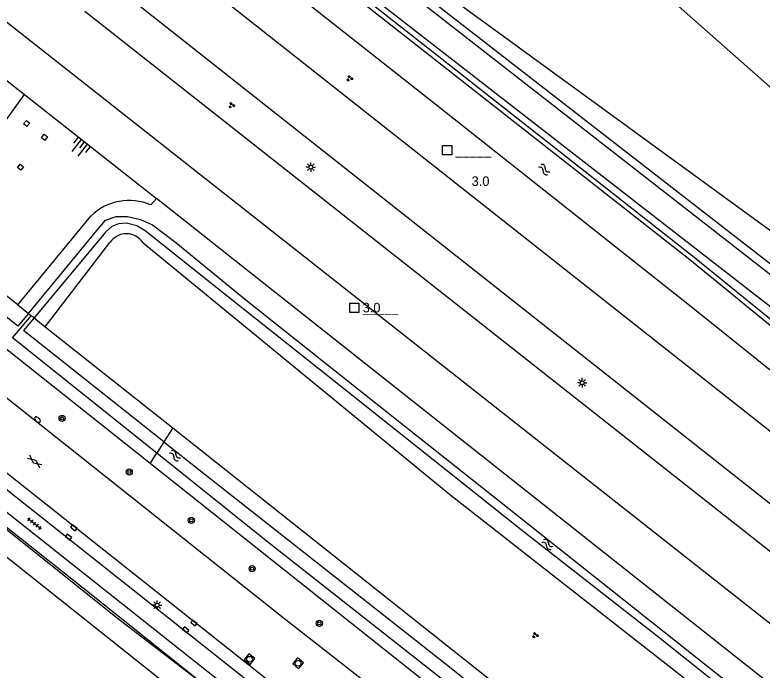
# Model space of a CAD drawing. Extents: x 136000 to 138005, y 398500 to 400500.
# Drawn here: x 136075.9 to 136173.3, y 399205.9 to 399291.4 of the extents above; entities that cross this region are included whole.
import ezdxf

# ---------------------------------------------------------------- set-up
doc = ezdxf.new("R2010")
doc.units = 0
for name, color, linetype in [('gg-afsc-faunaraster', 7, 'Continuous'), ('gg-afsc-hekwerk', 7, 'Continuous'), ('gg-aspt-spoorlijn', 7, 'Continuous'), ('gg-bbg-hoogspanningsmast', 7, 'Continuous'), ('gg-knt-BGT kruinlijn', 7, 'Continuous'), ('gg-knt-onverhard', 7, 'Continuous'), ('gg-knt-verharding', 7, 'Continuous'), ('gg-kntw-bovenkant insteek waterloop', 7, 'Continuous'), ('gg-kntw-waterlijn', 7, 'Continuous'), ('gt-anno-nummer hm paal', 7, 'Continuous'), ('gt-grn-groengrens', 7, 'Continuous'), ('gt-grn-vlakafsluiter', 7, 'Continuous'), ('gt-symb-boom', 7, 'Continuous'), ('gt-symb-brandkraan', 7, 'Continuous'), ('gt-symb-gesloten verharding', 7, 'Continuous'), ('gt-symb-groenvak', 7, 'Continuous'), ('gt-symb-hm paal', 7, 'Continuous'), ('gt-symb-kolk', 7, 'Continuous'), ('gt-symb-lichtmast', 7, 'Continuous'), ('gt-symb-rioolschacht', 7, 'Continuous'), ('gt-symb-talud symbool', 7, 'Continuous'), ('gt-symb-tegel verharding', 7, 'Continuous'), ('gt-symb-watersymbool', 7, 'Continuous')]:
    doc.layers.add(name, color=color, linetype=linetype)

# ---------------------------------------------------------------- blocks, each defined once
blk = doc.blocks.new('gt0-GRVAK')
at = {"layer": 'gt-symb-groenvak'}
for p, q in [((-0.11, 0.189), (-0.228, 0.24)), ((-0.182, 0.153), (0.088, 0.153)), ((-0.091, 0.211), (-0.156, 0.322)), ((-0.047, 0.214), (-0.047, 0.393)), ((-0.004, 0.211), (0.061, 0.322)), ((0.015, 0.189), (0.133, 0.24)), ((0.262, -0.052), (0.197, 0.059)), ((0.305, -0.049), (0.305, 0.13)), ((0.349, -0.052), (0.414, 0.059)), ((-0.245, -0.228), (-0.363, -0.177)), ((-0.318, -0.264), (-0.047, -0.264)), ((-0.226, -0.206), (-0.291, -0.095)), ((-0.183, -0.203), (-0.183, -0.024)), ((-0.139, -0.206), (-0.074, -0.095)), ((-0.12, -0.228), (-0.002, -0.177)), ((0.243, -0.074), (0.125, -0.023)), ((0.17, -0.11), (0.441, -0.11)), ((0.368, -0.074), (0.486, -0.023))]:
    blk.add_line(p, q, dxfattribs=at)
blk = doc.blocks.new('gt0-BR')
at = {"layer": 'gt-symb-brandkraan'}
for centre, radius, start, end in [((-0.244, 0), 0.206, 107.56694, 252.43307), ((0.599, -2.664), 3, 106.89205, 107.56694), ((0, -0.691), 0.938, 73.10799, 106.89205), ((-0.599, -2.664), 3, 72.43309, 73.10799), ((0.244, 0), 0.206, 287.56695, 72.43309), ((0.599, 2.664), 3, 252.43307, 253.10797), ((0, 0.691), 0.938, 253.10797, 286.89206), ((-0.599, 2.664), 3, 286.89206, 287.56695)]:
    blk.add_arc(centre, radius, start, end, dxfattribs=at)
blk = doc.blocks.new('gt0-BOOM')
at = {"layer": 'gt-symb-boom'}
for radius in [0.4, 0.2]:
    blk.add_circle((0, 0), radius, dxfattribs=at)
blk = doc.blocks.new('gt0-LMAST')
at = {"layer": 'gt-symb-lichtmast'}
for p, q in [((-0.182, 0.173), (-0.447, 0.438)), ((-0.005, 0.246), (-0.005, 0.621)), ((0.172, 0.173), (0.437, 0.438)), ((-0.255, -0.004), (-0.63, -0.004)), ((-0.182, -0.181), (-0.447, -0.446)), ((-0.005, -0.254), (-0.005, -0.629)), ((0.437, -0.446), (0.172, -0.181)), ((0.245, -0.004), (0.62, -0.004))]:
    blk.add_line(p, q, dxfattribs=at)
blk.add_circle((-0.005, -0.004), 0.25, dxfattribs=at)
blk = doc.blocks.new('gt0-HMpaal')
at = {"layer": 'gt-symb-hm paal'}
blk.add_lwpolyline([(-0.6, 0.6), (0.6, 0.6), (0.6, -0.6), (-0.6, -0.6)], close=True, dxfattribs=at)
blk = doc.blocks.new('gt0-KOLK')
at = {"layer": 'gt-symb-kolk'}
blk.add_lwpolyline([(0, 0), (0.375, 0), (0.375, 0.4), (-0.375, 0.4), (-0.375, 0), (0, 0)], dxfattribs=at)
blk = doc.blocks.new('gt0-RS')
at = {"layer": 'gt-symb-rioolschacht'}
blk.add_lwpolyline([(-0.5, -0.5), (0.5, -0.5), (0.5, 0.5), (-0.5, 0.5)], close=True, dxfattribs=at)
blk.add_circle((0, 0), 0.375, dxfattribs=at)
blk = doc.blocks.new('gt0-WA')
at = {"layer": 'gt-symb-watersymbool'}
for centre, start, end in [((-0.323, 0.022), 28.07249, 151.92751), ((0.427, 0.422), 208.07248, 331.92751), ((-0.323, -0.428), 28.07249, 151.92751), ((0.427, -0.028), 208.07248, 331.92751)]:
    blk.add_arc(centre, 0.425, start, end, dxfattribs=at)
blk = doc.blocks.new('gt0-TALUD_1')
at = {"layer": 'gt-symb-talud symbool'}
for p, q in [((-1, -1), (-1, 0)), ((-0.5, -2), (-0.5, 0)), ((0, -1), (0, 0)), ((0.5, -2), (0.5, 0)), ((1, -1), (1, 0))]:
    blk.add_line(p, q, dxfattribs=at)
blk = doc.blocks.new('gt0-TEG1')
at = {"layer": 'gt-symb-tegel verharding'}
for p, q in [((-1.125, 0), (1.125, 0)), ((-0.9, -0.25), (-0.9, 0.25)), ((-0.45, -0.25), (-0.45, 0.25)), ((0, -0.25), (0, 0.25)), ((0.45, -0.25), (0.45, 0.25)), ((0.9, -0.25), (0.9, 0.25))]:
    blk.add_line(p, q, dxfattribs=at)
blk = doc.blocks.new('gt0-GESVH1')
at = {"layer": 'gt-symb-gesloten verharding'}
for p, q in [((-0.992, -0.261), (0.008, 0.239)), ((0.008, -0.261), (-0.992, 0.239)), ((0.008, 0.239), (1.008, -0.261)), ((1.008, 0.239), (0.008, -0.261))]:
    blk.add_line(p, q, dxfattribs=at)

msp = doc.modelspace()

# ---------------------------------------------------------------- linework, layer by layer
at = {"layer": 'gg-afsc-faunaraster'}
msp.add_lwpolyline([(136214.317, 399220.192), (136203.22, 399228.666), (136186.783, 399241.641), (136164.492, 399259.74), (136130.358, 399286.558), (136068.733, 399334.937), (136035.885, 399360.173), (136022.676, 399370.363)], dxfattribs=at)
at = {"layer": 'gg-afsc-hekwerk'}
for points in [[(136127.206, 399323.659), (136215.131, 399246), (136215.693, 399247.287), (136216.642, 399250.086)], [(136056.17, 399235.463), (136100.954, 399199.876), (136105.557, 399195.919), (136110.005, 399191.964), (136114.179, 399187.825), (136118.653, 399183.499), (136124.986, 399177.048), (136129.086, 399172.587), (136131.034, 399170.324), (136134.011, 399166.352), (136133.48, 399165.332)]]:
    msp.add_lwpolyline(points, dxfattribs=at)
at = {"layer": 'gg-aspt-spoorlijn'}
for points in [[(136000, 399283.535), (136005.01, 399279.521), (136058.005, 399237.653), (136089.225, 399212.678), (136099.528, 399204.828)], [(136099.528, 399204.828), (136084.747, 399216.601), (136055.572, 399239.689)]]:
    msp.add_lwpolyline(points, dxfattribs=at)
at = {"layer": 'gg-bbg-hoogspanningsmast'}
for points in [[(136077.004, 399277.16), (136077.365, 399277.61), (136077.799, 399277.262), (136077.438, 399276.812), (136077.004, 399277.16)], [(136079.32, 399275.352), (136079.681, 399275.803), (136080.115, 399275.455), (136079.754, 399275.005), (136079.32, 399275.352)], [(136076.193, 399271.476), (136076.554, 399271.926), (136076.988, 399271.578), (136076.627, 399271.128), (136076.193, 399271.476)]]:
    msp.add_lwpolyline(points, dxfattribs=at)
at = {"layer": 'gg-knt-BGT kruinlijn'}
for p, q in [((136066.624, 399289.273), (136077.124, 399280.999)), ((136077.124, 399280.999), (136094.355, 399267.421))]:
    msp.add_line(p, q, dxfattribs=at)
at = {"layer": 'gg-knt-onverhard'}
for p, q in [((136025.433, 399373.792), (136199.467, 399237.96)), ((136196.985, 399235.716), (136023.141, 399370.942))]:
    msp.add_line(p, q, dxfattribs=at)
at = {"layer": 'gg-knt-verharding'}
msp.add_line((136062.349, 399241.518), (136189.361, 399140.818), dxfattribs=at)
for points in [[(136000, 399300.583), (136009.602, 399292.98), (136021.62, 399283.64), (136110.849, 399212.774), (136149.976, 399182.139), (136156.723, 399176.954), (136163.603, 399171.956), (136180.996, 399160.126), (136190.325, 399153.487), (136197.172, 399148.355)], [(136088.112, 399295.795), (136207.72, 399201.356), (136219.722, 399192.611), (136226.153, 399188.055), (136232.623, 399183.556), (136243.765, 399175.907), (136254.967, 399168.345), (136265.054, 399161.702), (136275.227, 399155.193), (136288.44, 399146.994), (136296.982, 399141.832)], [(136070.342, 399293.959), (136070.79, 399293.604), (136203.448, 399189.114), (136211.914, 399182.913), (136219.756, 399177.358), (136227.638, 399171.859), (136237.572, 399165.006), (136247.572, 399158.248), (136257.91, 399151.482), (136268.333, 399144.849), (136294.647, 399128.702)], [(136103.258, 399293.201), (136212.245, 399207.21), (136214.457, 399205.603)], [(136272.629, 399150.781), (136262.277, 399157.402), (136252.002, 399164.143), (136242.228, 399170.714), (136232.518, 399177.379), (136224.412, 399183.047), (136216.35, 399188.777), (136207.923, 399194.944), (136084.971, 399291.816)], [(136182.349, 399139.919), (136183.02, 399140.66), (136056.518, 399240.929)], [(136061.183, 399240.189), (136183.204, 399143.484), (136188.353, 399139.298)]]:
    msp.add_lwpolyline(points, dxfattribs=at)
at = {"layer": 'gg-kntw-bovenkant insteek waterloop'}
for p, q in [((136093.598, 399266.598), (136094.355, 399267.421)), ((136199.873, 399183.926), (136094.355, 399267.421)), ((136076.241, 399253.54), (136085.762, 399265.111)), ((136076.241, 399253.54), (136066.079, 399261.6)), ((136079.823, 399250.699), (136088.253, 399261.676)), ((136079.823, 399250.699), (136096.472, 399237.494)), ((136093.501, 399232.868), (136074.451, 399247.994)), ((136133.247, 399201.311), (136093.501, 399232.868))]:
    msp.add_line(p, q, dxfattribs=at)
for points in [[(136000, 399386.956), (136035.518, 399359.572), (136068.097, 399334.964), (136099.621, 399309.977), (136163.904, 399259.481), (136186.321, 399241.156), (136202.703, 399228.356), (136214.317, 399220.192)], [(136000, 399382.438), (136021.417, 399365.772), (136066.425, 399330.419), (136131.087, 399279.488), (136164.066, 399253.351), (136198.116, 399226.045), (136212.682, 399215.577), (136221.955, 399208.076), (136223.567, 399206.325)], [(136092.581, 399261.652), (136132.569, 399228.879), (136196.134, 399179.093)], [(136096.472, 399237.494), (136148.559, 399196.182), (136154.882, 399193.191), (136161.043, 399189.879), (136182.919, 399176.921), (136187.749, 399173.888), (136195.808, 399168.53)]]:
    msp.add_lwpolyline(points, dxfattribs=at)
for centre, radius, start, end in [((136090.787, 399260.021), 7.153, 66.85892, 134.63105), ((136090.409, 399260.252), 2.584, 32.80336, 146.5612)]:
    msp.add_arc(centre, radius, start, end, dxfattribs=at)
at = {"layer": 'gg-kntw-waterlijn'}
for p, q in [((136076.245, 399250.798), (136054.547, 399268.009)), ((136077.621, 399252.446), (136076.245, 399250.798)), ((136078.357, 399251.862), (136076.981, 399250.213)), ((136095.306, 399235.678), (136076.981, 399250.213)), ((136094.36, 399234.205), (136075.542, 399249.27))]:
    msp.add_line(p, q, dxfattribs=at)
for points in [[(136077.621, 399252.446), (136081.1, 399256.65), (136086.765, 399263.496), (136087.699, 399264.624), (136089.083, 399265.101), (136090.547, 399265.098), (136092.238, 399264.712), (136093.824, 399264.01), (136096.84, 399261.689), (136105.98, 399254.214), (136122.534, 399241.07), (136139.088, 399227.927), (136172.765, 399201.188)], [(136182.154, 399192.397), (136159.849, 399210.145), (136141.927, 399224.201), (136117.042, 399243.973), (136104.166, 399254.203), (136092.838, 399263.204), (136091.785, 399263.882), (136090.4, 399264.213), (136089.386, 399264.13), (136088.503, 399263.769), (136087.671, 399263.017), (136078.357, 399251.862)], [(136095.306, 399235.678), (136100.67, 399231.423), (136132.56, 399206.333), (136146.848, 399194.877), (136151.889, 399191.94), (136157.035, 399189.796), (136162.984, 399186.82), (136167.596, 399184.115), (136182.012, 399175.662), (136191.645, 399169.35), (136205.559, 399159.025), (136205.96, 399158.735)], [(136204.94, 399157.301), (136194.847, 399164.788), (136180.535, 399174.567), (136175.284, 399177.682), (136162.221, 399185.431), (136157.772, 399187.71), (136151.255, 399190.355), (136146.376, 399193.059), (136108.639, 399222.774), (136094.36, 399234.205)]]:
    msp.add_lwpolyline(points, dxfattribs=at)
at = {"layer": 'gt-grn-groengrens'}
for points in [[(136216.166, 399233.164), (136213.916, 399235.179), (136212.061, 399236.526), (136211.863, 399235.941), (136120.273, 399302.685), (136119.623, 399301.487)], [(136119.623, 399301.487), (136176.178, 399257.548), (136208.245, 399232.585)], [(136066.079, 399261.6), (136068.801, 399269.523), (136077.124, 399280.999)]]:
    msp.add_lwpolyline(points, dxfattribs=at)
at = {"layer": 'gt-grn-vlakafsluiter'}
for p, q in [((136076.241, 399253.54), (136077.621, 399252.446)), ((136075.542, 399249.27), (136078.001, 399252.144)), ((136077.621, 399252.446), (136078.001, 399252.144)), ((136078.357, 399251.862), (136078.001, 399252.144)), ((136078.357, 399251.862), (136079.823, 399250.699)), ((136096.472, 399237.494), (136095.306, 399235.678)), ((136095.306, 399235.678), (136094.36, 399234.205)), ((136093.501, 399232.868), (136094.36, 399234.205))]:
    msp.add_line(p, q, dxfattribs=at)

# ---------------------------------------------------------------- block references
at = {"layer": 'gt-symb-boom'}
for p in [(136082.02, 399238.737), (136090.777, 399231.761), (136098.873, 399225.451), (136106.815, 399219.139), (136115.571, 399212.012)]:
    msp.add_blockref('gt0-BOOM', p, dxfattribs=at)
at = {"layer": 'gt-symb-brandkraan', "rotation": -38.25701687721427}
msp.add_blockref('gt0-BR', (136078.806, 399238.586), dxfattribs=at)
at = {"layer": 'gt-symb-gesloten verharding', "rotation": -38.66875373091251}
msp.add_blockref('gt0-GESVH1', (136078.442, 399233.134), dxfattribs=at)
at = {"layer": 'gt-symb-groenvak'}
for p in [(136119.523, 399283.087), (136104.118, 399279.589), (136143.728, 399210.455)]:
    msp.add_blockref('gt0-GRVAK', p, dxfattribs=at)
at = {"layer": 'gt-symb-hm paal'}
for p in [(136132.258, 399273.736), (136120.148, 399253.177)]:
    msp.add_blockref('gt0-HMpaal', p, dxfattribs=at)
at = {"layer": 'gt-symb-kolk'}
for p, rotation in [((136083.672, 399224.634), 141.00900595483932), ((136082.736, 399223.111), -38.30199383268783), ((136099.343, 399212.213), 141.61754266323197), ((136098.02, 399211.001), -38.221556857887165)]:
    msp.add_blockref('gt0-KOLK', p, dxfattribs=dict(at, rotation=rotation))
at = {"layer": 'gt-symb-lichtmast'}
for p in [(136114.472, 399271.522), (136149.869, 399243.394), (136094.418, 399214.385)]:
    msp.add_blockref('gt0-LMAST', p, dxfattribs=at)
at = {"layer": 'gt-symb-rioolschacht'}
for p, rotation in [((136106.479, 399207.328), -38.382457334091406), ((136112.805, 399206.794), 140.1136996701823)]:
    msp.add_blockref('gt0-RS', p, dxfattribs=dict(at, rotation=rotation))
at = {"layer": 'gt-symb-talud symbool', "xscale": 0.999692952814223, "yscale": 0.999692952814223, "rotation": -38.25701687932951}
msp.add_blockref('gt0-TALUD_1', (136084.959, 399274.825), dxfattribs=at)
at = {"layer": 'gt-symb-tegel verharding', "rotation": -38.382457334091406}
msp.add_blockref('gt0-TEG1', (136078.422, 399225.027), dxfattribs=at)
at = {"layer": 'gt-symb-watersymbool'}
for p, rotation in [((136144.869, 399271.236), -37.64891642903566), ((136096.688, 399233.927), -37.23665897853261), ((136145.289, 399222.335), -33.499400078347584)]:
    msp.add_blockref('gt0-WA', p, dxfattribs=dict(at, rotation=rotation))

# ---------------------------------------------------------------- texts
at = {"layer": 'gt-anno-nummer hm paal'}
for p in [(136135.443, 399269.068), (136121.229, 399252.573)]:
    msp.add_text('3.0', height=1.25, dxfattribs=at).set_placement(p)
at = {"layer": 'gt-symb-hm paal'}
for p in [(136133.339, 399273.132), (136121.229, 399252.573)]:
    msp.add_text('_____', height=1.25, dxfattribs=at).set_placement(p)

doc.saveas('drawing.dxf')
